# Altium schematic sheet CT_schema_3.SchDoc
size 276 x 169 mm
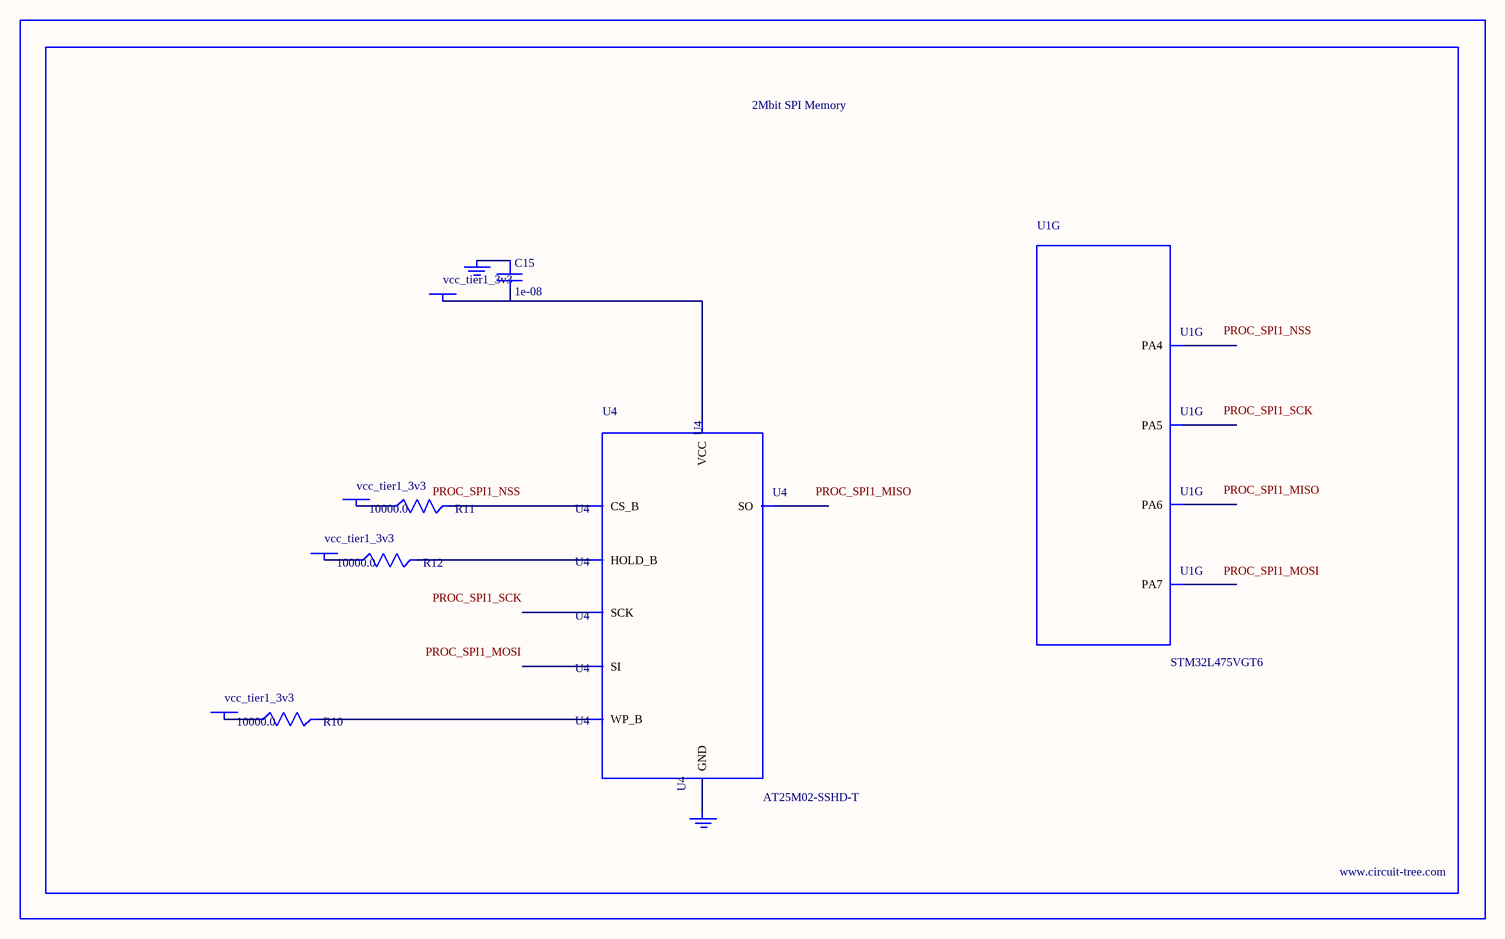
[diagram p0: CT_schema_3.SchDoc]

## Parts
BORDER2  (no value)
C15  1e-08  [C0402]
GND_INSTANCE_2_0  (no value)
GND_INSTANCE_2_1  (no value)
POWER_INSTANCE_2_0  vcc_tier1_3v3
POWER_INSTANCE_2_1  vcc_tier1_3v3
POWER_INSTANCE_2_2  vcc_tier1_3v3
POWER_INSTANCE_2_3  vcc_tier1_3v3
R10  10000.0  [R0603]
R11  10000.0  [R0603]
R12  10000.0  [R0603]
U1  STM32L475VGT6  [LQFP100]  (part G of 11)
U4  AT25M02-SSHD-T  [SOIC-8]

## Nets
NetC15_1: C15.1 GND_INSTANCE_2_0.0(GND)
NetC15_2: C15.2 POWER_INSTANCE_2_3.0(PWR) U4.8(VCC)
NetGND_INSTANCE_2_1_0: GND_INSTANCE_2_1.0(GND) U4.4(GND)
NetPOWER_INSTANCE_2_0_0: POWER_INSTANCE_2_0.0(PWR) R11.1
NetPOWER_INSTANCE_2_1_0: POWER_INSTANCE_2_1.0(PWR) R10.1
NetPOWER_INSTANCE_2_2_0: POWER_INSTANCE_2_2.0(PWR) R12.1
NetR10_2: R10.2 U4.3(WP_B)
NetR11_2: R11.2 U4.1(CS_B)
NetR12_2: R12.2 U4.7(HOLD_B)

Not connected (* = marked no-connect by the designer): U1 29(PA4) 30(PA5) 31(PA6) 32(PA7); U4 2(SO) 5(SI) 6(SCK)

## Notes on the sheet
- Labels drawn without touching a wire or pin: PROC_SPI1_MISO, PROC_SPI1_MOSI, PROC_SPI1_NSS, PROC_SPI1_SCK

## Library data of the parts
BORDER2 = BORDER_PAGE2
C15 = C0402C103K3RAC
GND_INSTANCE_2_0 GND_INSTANCE_2_1 = GND
POWER_INSTANCE_2_0-POWER_INSTANCE_2_3 = PWR
R10-R12 = RC0603JR-0710KL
